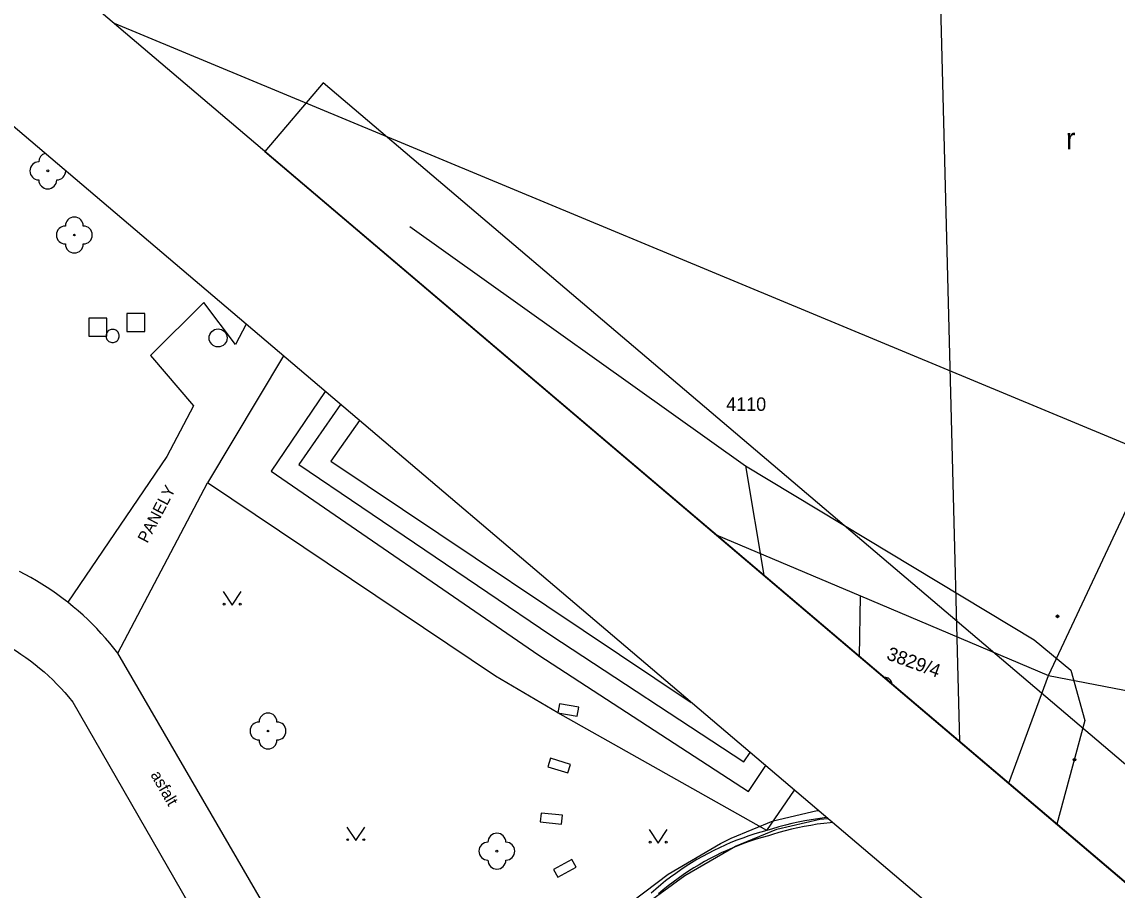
# Model space of a CAD drawing. Extents: x -540150 to -533593, y -1185082 to -1180066.
# Drawn here: x -536273 to -536212, y -1184738.1 to -1184689.8 of the extents above; entities that cross this region are included whole.
import ezdxf

# ---------------------------------------------------------------- set-up
doc = ezdxf.new("R2010")
doc.units = 0
for name, color, linetype in [('KN_HRAN_PARCEL', 7, 'Continuous'), ('KN_PARC_Č', 7, 'Continuous'), ('KN_VKP_HRAN_', 7, 'Continuous'), ('rámeček', 7, 'Continuous'), ('Vrstva 1', 7, 'Continuous'), ('Vrstva 10', 7, 'Continuous'), ('Vrstva 11', 7, 'Continuous'), ('Vrstva 14', 7, 'Continuous'), ('Vrstva 20', 7, 'Continuous'), ('Vrstva 21', 7, 'Continuous'), ('Vrstva 22', 7, 'Continuous'), ('Vrstva 26', 7, 'Continuous'), ('Vrstva 27', 7, 'Continuous'), ('Vrstva 36', 7, 'Continuous'), ('Vrstva 40', 7, 'Continuous')]:
    doc.layers.add(name, color=color, linetype=linetype)

msp = doc.modelspace()

# ---------------------------------------------------------------- linework, layer by layer
at = {"layer": 'KN_HRAN_PARCEL'}
for p, q in [((-536267.873, -1184689.83), (-536210.051, -1184713.855)), ((-536215.831, -1184726.145), (-536210.051, -1184713.855)), ((-536234.333, -1184718.312), (-536226.301, -1184721.715)), ((-536226.354, -1184725.087), (-536226.301, -1184721.715)), ((-536226.301, -1184721.715), (-536215.831, -1184726.145)), ((-536218.04, -1184732.147), (-536215.831, -1184726.145)), ((-536215.831, -1184726.145), (-536087.491, -1184751.215))]:
    msp.add_line(p, q, dxfattribs=at)
at = {"layer": 'KN_VKP_HRAN_'}
for p, q in [((-536231.162, -1184734.251), (-536228.712, -1184733.671)), ((-536228.712, -1184733.671), (-536228.638, -1184733.665)), ((-536233.492, -1184735.211), (-536231.162, -1184734.251)), ((-536230.962, -1184734.711), (-536228.552, -1184734.151)), ((-536228.552, -1184734.151), (-536228.102, -1184734.12)), ((-536233.262, -1184735.651), (-536230.962, -1184734.711)), ((-536237.002, -1184737.211), (-536234.092, -1184735.501)), ((-536236.082, -1184737.291), (-536233.262, -1184735.651)), ((-536234.092, -1184735.501), (-536233.492, -1184735.211)), ((-536239.692, -1184739.241), (-536237.002, -1184737.211)), ((-536239.042, -1184739.441), (-536236.082, -1184737.291))]:
    msp.add_line(p, q, dxfattribs=at)
at = {"layer": 'rámeček'}
msp.add_lwpolyline([(-536863.363, -1184184.148), (-536677.591, -1183965.383), (-535884.856, -1184638.563), (-536070.628, -1184857.328)], close=True, dxfattribs=at)
for points in [[(-537054.324, -1184409.023), (-536261.589, -1185082.203), (-536075.817, -1184863.438), (-536868.552, -1184190.259)], [(-536067.391, -1184853.516), (-536256.235, -1184693.153), (-536259.471, -1184696.965)], [(-536259.471, -1184696.965), (-536070.628, -1184857.328), (-536067.391, -1184853.516)]]:
    msp.add_lwpolyline(points, dxfattribs=at)
at = {"layer": 'Vrstva 1'}
msp.add_lwpolyline([(-536220.766, -1184729.832), (-536222.951, -1184645.004), (-536226.092, -1184581.816)], dxfattribs=at)
at = {"layer": 'Vrstva 10'}
for p, q in [((-536257.729, -1184742.002), (-536267.662, -1184724.901)), ((-536270.172, -1184727.631), (-536263.722, -1184738.871))]:
    msp.add_line(p, q, dxfattribs=at)
for points in [[(-536267.662, -1184724.901), (-536267.884, -1184724.619), (-536268.113, -1184724.342), (-536268.348, -1184724.07), (-536268.589, -1184723.803), (-536268.835, -1184723.542), (-536269.088, -1184723.286), (-536269.346, -1184723.036), (-536269.609, -1184722.792), (-536269.878, -1184722.553), (-536270.152, -1184722.321), (-536270.462, -1184722.071), (-536270.716, -1184721.875), (-536271.005, -1184721.662), (-536271.299, -1184721.455), (-536271.597, -1184721.254), (-536271.899, -1184721.061), (-536272.206, -1184720.874), (-536272.517, -1184720.694), (-536272.832, -1184720.521), (-536273.151, -1184720.355)], [(-536274.754, -1184723.989), (-536274.463, -1184724.133), (-536274.175, -1184724.285), (-536273.891, -1184724.444), (-536273.611, -1184724.61), (-536273.335, -1184724.782), (-536273.064, -1184724.962), (-536272.797, -1184725.147), (-536272.535, -1184725.34), (-536272.277, -1184725.539), (-536272.025, -1184725.744), (-536271.778, -1184725.955), (-536271.536, -1184726.172), (-536271.299, -1184726.395), (-536271.068, -1184726.624), (-536270.842, -1184726.859), (-536270.623, -1184727.099), (-536270.409, -1184727.344), (-536270.172, -1184727.631)]]:
    msp.add_lwpolyline(points, dxfattribs=at)
at = {"layer": 'Vrstva 11'}
for p, q in [((-536258.447, -1184708.352), (-536262.682, -1184715.421)), ((-536256.112, -1184710.334), (-536259.132, -1184714.771)), ((-536263.452, -1184711.141), (-536264.932, -1184713.961)), ((-536255.261, -1184711.057), (-536257.592, -1184714.401)), ((-536264.932, -1184713.961), (-536270.462, -1184722.071)), ((-536257.592, -1184714.401), (-536243.552, -1184723.911)), ((-536259.132, -1184714.771), (-536244.222, -1184725.021)), ((-536267.662, -1184724.901), (-536262.682, -1184715.421)), ((-536243.552, -1184723.911), (-536232.802, -1184730.951)), ((-536244.222, -1184725.021), (-536232.532, -1184732.611)), ((-536232.802, -1184730.951), (-536232.448, -1184730.43)), ((-536232.532, -1184732.611), (-536231.575, -1184731.171)), ((-536231.189, -1184734.68), (-536231.512, -1184734.781)), ((-536231.192, -1184735), (-536231.418, -1184735.072))]:
    msp.add_line(p, q, dxfattribs=at)
for points in [[(-536262.882, -1184705.381), (-536265.842, -1184708.331), (-536263.452, -1184711.141)], [(-536260.522, -1184706.589), (-536261.112, -1184707.711), (-536262.882, -1184705.381)], [(-536267.658, -1184707.446), (-536267.631, -1184707.399), (-536267.611, -1184707.349), (-536267.599, -1184707.296), (-536267.595, -1184707.242), (-536267.599, -1184707.188), (-536267.611, -1184707.135), (-536267.63, -1184707.084), (-536267.657, -1184707.037), (-536267.69, -1184706.995), (-536267.729, -1184706.957), (-536267.773, -1184706.926), (-536267.822, -1184706.902), (-536267.873, -1184706.885), (-536267.927, -1184706.876), (-536267.981, -1184706.874), (-536268.034, -1184706.881), (-536268.087, -1184706.896), (-536268.136, -1184706.918), (-536268.182, -1184706.947), (-536268.223, -1184706.982), (-536268.258, -1184707.024), (-536268.287, -1184707.069), (-536268.308, -1184707.119), (-536268.322, -1184707.171), (-536268.329, -1184707.225), (-536268.327, -1184707.279), (-536268.318, -1184707.333), (-536268.3, -1184707.384), (-536268.275, -1184707.432), (-536268.244, -1184707.476), (-536268.206, -1184707.515), (-536268.163, -1184707.548), (-536268.116, -1184707.574), (-536268.065, -1184707.593), (-536268.012, -1184707.605), (-536267.958, -1184707.608), (-536267.904, -1184707.604), (-536267.852, -1184707.591), (-536267.801, -1184707.571), (-536267.754, -1184707.544), (-536267.712, -1184707.51), (-536267.675, -1184707.47), (-536267.658, -1184707.446)], [(-536243.152, -1184728.221), (-536242.074, -1184728.42), (-536241.982, -1184727.921), (-536243.06, -1184727.722), (-536243.152, -1184728.221)], [(-536243.562, -1184730.751), (-536243.711, -1184731.228), (-536242.591, -1184731.578), (-536242.442, -1184731.101), (-536243.562, -1184730.751)], [(-536244.082, -1184733.811), (-536244.133, -1184734.308), (-536242.953, -1184734.428), (-536242.902, -1184733.931), (-536244.082, -1184733.811)], [(-536227.849, -1184734.335), (-536227.983, -1184734.348), (-536228.345, -1184734.389), (-536228.706, -1184734.438), (-536229.066, -1184734.495), (-536229.425, -1184734.56), (-536229.782, -1184734.632), (-536230.137, -1184734.712), (-536230.491, -1184734.801), (-536230.842, -1184734.897), (-536231.192, -1184735)], [(-536228.172, -1184734.061), (-536228.313, -1184734.077), (-536228.678, -1184734.125), (-536229.041, -1184734.181), (-536229.403, -1184734.244), (-536229.764, -1184734.316), (-536230.123, -1184734.395), (-536230.481, -1184734.482), (-536230.836, -1184734.577), (-536231.189, -1184734.68)], [(-536231.512, -1184734.781), (-536231.852, -1184734.875), (-536232.189, -1184734.976), (-536232.524, -1184735.086), (-536232.857, -1184735.202), (-536233.187, -1184735.327), (-536233.514, -1184735.458), (-536233.837, -1184735.597), (-536234.158, -1184735.744), (-536234.475, -1184735.898), (-536234.789, -1184736.058), (-536235.099, -1184736.226), (-536235.405, -1184736.401), (-536235.707, -1184736.583), (-536236.005, -1184736.772), (-536236.298, -1184736.967), (-536236.587, -1184737.169), (-536236.871, -1184737.377), (-536237.15, -1184737.592), (-536237.425, -1184737.813), (-536237.694, -1184738.04), (-536237.958, -1184738.274)], [(-536231.418, -1184735.072), (-536231.77, -1184735.17), (-536232.104, -1184735.271), (-536232.436, -1184735.379), (-536232.765, -1184735.495), (-536233.092, -1184735.618), (-536233.415, -1184735.749), (-536233.736, -1184735.887), (-536234.053, -1184736.033), (-536234.367, -1184736.185), (-536234.677, -1184736.345), (-536234.983, -1184736.512), (-536235.286, -1184736.686), (-536235.584, -1184736.867), (-536235.878, -1184737.055), (-536236.168, -1184737.249), (-536236.454, -1184737.45), (-536236.734, -1184737.657), (-536237.01, -1184737.871), (-536237.281, -1184738.091), (-536237.547, -1184738.317)], [(-536243.402, -1184736.951), (-536243.161, -1184737.389), (-536242.141, -1184736.829), (-536242.382, -1184736.391), (-536243.402, -1184736.951)]]:
    msp.add_lwpolyline(points, dxfattribs=at)
at = {"layer": 'Vrstva 14'}
for p, q in [((-536254.207, -1184711.952), (-536255.802, -1184714.221)), ((-536255.802, -1184714.221), (-536235.724, -1184727.648)), ((-536246.632, -1184726.191), (-536262.682, -1184715.421)), ((-536243.152, -1184728.221), (-536246.632, -1184726.191)), ((-536231.512, -1184734.781), (-536243.152, -1184728.221)), ((-536231.512, -1184734.781), (-536229.979, -1184732.527))]:
    msp.add_line(p, q, dxfattribs=at)
at = {"layer": 'Vrstva 20'}
for centre, radius in [((-536215.321, -1184722.855), 0.075), ((-536215.321, -1184722.855), 0.0204), ((-536214.371, -1184730.835), 0.075), ((-536214.371, -1184730.835), 0.0204)]:
    msp.add_circle(centre, radius, dxfattribs=at)
at = {"layer": 'Vrstva 21'}
for points in [[(-536251.401, -1184701.155), (-536232.701, -1184714.475)], [(-536232.701, -1184714.475), (-536231.682, -1184720.562)], [(-536232.701, -1184714.475), (-536216.621, -1184724.155), (-536214.581, -1184725.855), (-536213.791, -1184728.665), (-536215.352, -1184734.43)]]:
    msp.add_lwpolyline(points, dxfattribs=at)
at = {"layer": 'Vrstva 22'}
for centre in [(-536271.572, -1184698.051), (-536270.092, -1184701.621), (-536259.302, -1184729.241), (-536246.552, -1184735.931)]:
    msp.add_circle(centre, 0.05, dxfattribs=at)
for centre, start, end in [((-536271.572, -1184697.551), 107.95062, 180), ((-536272.072, -1184698.051), 90, 270), ((-536271.572, -1184698.551), 180, 0), ((-536271.072, -1184698.051), 270, 359.49952), ((-536270.092, -1184701.121), 0, 180), ((-536270.592, -1184701.621), 90, 270), ((-536269.592, -1184701.621), 270, 90), ((-536270.092, -1184702.121), 180, 0), ((-536259.302, -1184728.741), 0, 180), ((-536259.802, -1184729.241), 90, 270), ((-536258.802, -1184729.241), 270, 90), ((-536259.302, -1184729.741), 180, 0), ((-536246.552, -1184735.431), 0, 180), ((-536247.052, -1184735.931), 90, 270), ((-536246.052, -1184735.931), 270, 90), ((-536246.552, -1184736.431), 180, 0)]:
    msp.add_arc(centre, 0.5, start, end, dxfattribs=at)
at = {"layer": 'Vrstva 26'}
for points in [[(-536269.282, -1184707.261), (-536268.282, -1184707.261), (-536268.282, -1184706.261), (-536269.282, -1184706.261)], [(-536267.172, -1184707.001), (-536266.172, -1184707.001), (-536266.172, -1184706.001), (-536267.172, -1184706.001)]]:
    msp.add_lwpolyline(points, close=True, dxfattribs=at)
at = {"layer": 'Vrstva 27'}
msp.add_circle((-536262.082, -1184707.351), 0.5, dxfattribs=at)
at = {"layer": 'Vrstva 36'}
for p, q in [((-536224.961, -1184726.27), (-536224.701, -1184726.491)), ((-536224.089, -1184727.011), (-536224.047, -1184727.011))]:
    msp.add_line(p, q, dxfattribs=at)
for points in [[(-536261.799, -1184721.481), (-536261.299, -1184722.231), (-536260.799, -1184721.481)], [(-536254.914, -1184734.593), (-536254.414, -1184735.343), (-536253.914, -1184734.593)], [(-536238.064, -1184734.73), (-536237.564, -1184735.48), (-536237.064, -1184734.73)]]:
    msp.add_lwpolyline(points, dxfattribs=at)
for centre in [(-536261.749, -1184722.18), (-536260.85, -1184722.18), (-536254.864, -1184735.292), (-536253.965, -1184735.292), (-536238.014, -1184735.429), (-536237.115, -1184735.429)]:
    msp.add_circle(centre, 0.05, dxfattribs=at)
for centre, start, end in [((-536224.922, -1184726.635), 2.14609, 97.17897), ((-536225.047, -1184726.635), 22.67956, 76.64551)]:
    msp.add_arc(centre, 0.375, start, end, dxfattribs=at)

# ---------------------------------------------------------------- texts
at = {"layer": 'KN_PARC_Č'}
msp.add_text('4110', height=0.75, dxfattribs=at).set_placement((-536233.781, -1184711.415))
msp.add_text('3829/4', height=0.75, rotation=340, dxfattribs=at).set_placement((-536224.89, -1184725.234))
at = {"layer": 'Vrstva 36'}
msp.add_text('r', height=1.2, dxfattribs=at).set_placement((-536214.855, -1184696.857))
at = {"layer": 'Vrstva 40'}
for s, rotation, p in [('PANELY', 62.28631, (-536266.028, -1184718.821)), ('asfalt', 299.84907, (-536265.868, -1184731.676))]:
    msp.add_text(s, height=0.65, rotation=rotation, dxfattribs=at).set_placement(p)

doc.saveas('drawing.dxf')
